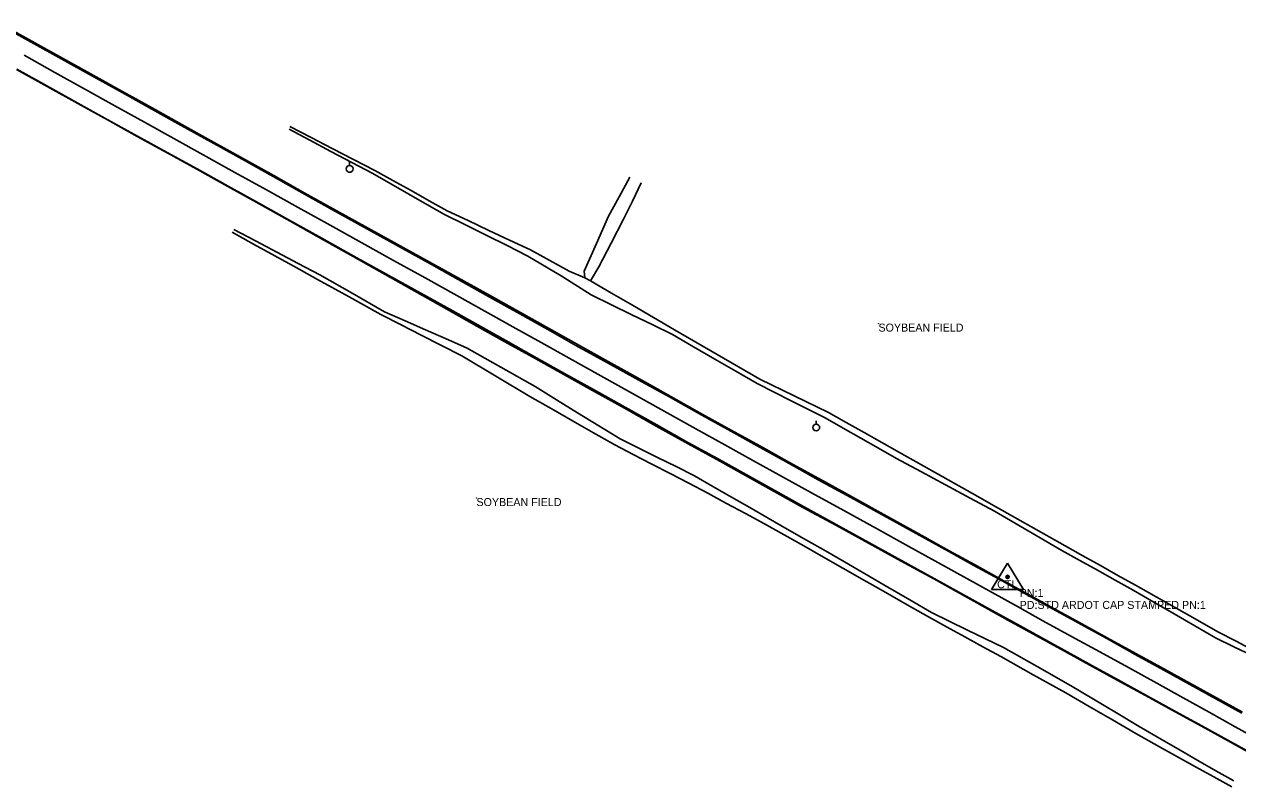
# Model space of a CAD drawing. Extents: x 1411444 to 1458157, y 300965 to 327300.
# Drawn here: x 1452975 to 1453733, y 303315 to 303791 of the extents above; entities that cross this region are included whole.
import ezdxf

# ---------------------------------------------------------------- set-up
doc = ezdxf.new("R2010")
doc.units = 0
for name, color, linetype in [('S_DITCHLINE', 7, 'Continuous'), ('S_EDGE_PAVEMENT', 7, 'Continuous'), ('S_MSC_PT_SYM', 7, 'Continuous'), ('S_PAVEMENT_CROWN', 7, 'Continuous'), ('S_PRIMARY_CTL', 7, 'Continuous'), ('S_PRIMARY_CTL_ANNOT', 7, 'Continuous'), ('S_SHOULDER', 7, 'Continuous'), ('S_SURVEY_TEXT_ANNOT', 7, 'Continuous'), ('S_UTILITY_POLE', 7, 'Continuous')]:
    doc.layers.add(name, color=color, linetype=linetype)

msp = doc.modelspace()

# ---------------------------------------------------------------- linework, layer by layer
at = {"layer": 'S_DITCHLINE'}
for points in [[(1453141.09, 303727.61), (1453154.33, 303720.74), (1453167.58, 303713.87), (1453180.83, 303706.99), (1453194.08, 303700.12), (1453205.42, 303693.81), (1453216.76, 303687.5), (1453228.1, 303681.19), (1453239.44, 303674.88), (1453252.42, 303668.76), (1453265.39, 303662.64), (1453278.37, 303656.53), (1453291.35, 303650.41), (1453303.47, 303643.81), (1453315.6, 303637.22), (1453325.3, 303633.05), (1453328.86, 303631.15), (1453341.98, 303623.5), (1453355.1, 303615.86), (1453368.22, 303608.22), (1453381.34, 303600.57), (1453394.67, 303592.82), (1453408, 303585.06), (1453421.33, 303577.31), (1453434.66, 303569.56), (1453456.1, 303559.14), (1453477.55, 303548.72), (1453488.67, 303542.47), (1453499.8, 303536.22), (1453510.93, 303529.97), (1453522.05, 303523.72), (1453537.19, 303515.2), (1453552.33, 303506.68), (1453567.47, 303498.16), (1453582.61, 303489.64), (1453604.08, 303477.53), (1453625.55, 303465.42), (1453636.5, 303459.26), (1453647.46, 303453.11), (1453658.41, 303446.95), (1453669.37, 303440.8), (1453682.26, 303433.51), (1453695.15, 303426.22), (1453708.04, 303418.94), (1453720.93, 303411.65), (1453732.25, 303405.79), (1453743.57, 303399.94)], [(1453140.54, 303725.91), (1453153.65, 303718.98), (1453166.77, 303712.05), (1453179.88, 303705.12), (1453193, 303698.19), (1453204.2, 303691.77), (1453215.39, 303685.35), (1453226.59, 303678.93), (1453237.78, 303672.51), (1453250.8, 303666.04), (1453263.81, 303659.57), (1453276.83, 303653.1), (1453289.84, 303646.63), (1453310.56, 303634.31), (1453329.37, 303622.31), (1453342.06, 303616.11), (1453354.76, 303609.92), (1453367.45, 303603.73), (1453380.14, 303597.53), (1453393.34, 303589.87), (1453406.54, 303582.22), (1453419.74, 303574.56), (1453432.94, 303566.9), (1453454.25, 303556.17), (1453475.55, 303545.43), (1453486.67, 303539.11), (1453497.79, 303532.8), (1453508.91, 303526.48), (1453520.03, 303520.16), (1453535.37, 303511.9), (1453550.7, 303503.63), (1453566.03, 303495.37), (1453581.36, 303487.1), (1453602.42, 303474.84), (1453623.48, 303462.59), (1453634.59, 303456.39), (1453645.69, 303450.19), (1453656.8, 303443.99), (1453667.91, 303437.8), (1453680.76, 303430.34), (1453693.61, 303422.89), (1453706.45, 303415.44), (1453719.3, 303407.99), (1453730.77, 303402.44), (1453742.23, 303396.89)], [(1453353.38, 303695.85), (1453346.77, 303683.72), (1453340.16, 303671.59), (1453332.56, 303654.35), (1453324.96, 303637.11), (1453325.28, 303633.06)], [(1453360.63, 303692.29), (1453355.04, 303680.94), (1453349.45, 303669.6), (1453341.81, 303654.71), (1453334.17, 303639.82), (1453328.89, 303631.12)], [(1453104.96, 303661.46), (1453118.32, 303654.1), (1453131.69, 303646.75), (1453145.06, 303639.4), (1453158.42, 303632.05), (1453178.13, 303621.06), (1453197.84, 303610.07), (1453210.52, 303603.6), (1453223.19, 303597.13), (1453235.87, 303590.66), (1453248.54, 303584.19), (1453269.79, 303571.49), (1453291.03, 303558.79), (1453304.29, 303551.23), (1453317.56, 303543.67), (1453330.82, 303536.11), (1453344.08, 303528.56), (1453355.64, 303522.58), (1453367.19, 303516.6), (1453378.74, 303510.62), (1453390.3, 303504.65), (1453402.13, 303498.31), (1453413.97, 303491.98), (1453425.81, 303485.64), (1453437.65, 303479.31), (1453449.89, 303472.35), (1453462.14, 303465.39), (1453474.38, 303458.43), (1453486.63, 303451.47), (1453499.99, 303443.88), (1453513.36, 303436.29), (1453526.73, 303428.7), (1453540.09, 303421.11), (1453551.39, 303414.89), (1453562.68, 303408.66), (1453573.98, 303402.44), (1453585.27, 303396.21), (1453605.56, 303384.9), (1453625.85, 303373.58), (1453640.46, 303365.14), (1453655.08, 303356.69), (1453669.7, 303348.24), (1453684.32, 303339.8), (1453695.65, 303333.57), (1453706.97, 303327.35), (1453718.3, 303321.12), (1453729.63, 303314.9)], [(1453106.11, 303663.12), (1453119.5, 303656.05), (1453132.9, 303648.99), (1453146.3, 303641.92), (1453159.7, 303634.85), (1453179.95, 303623.34), (1453200.19, 303611.82), (1453213.01, 303606.18), (1453225.82, 303600.54), (1453238.63, 303594.89), (1453251.44, 303589.25), (1453272.84, 303577.12), (1453294.23, 303564.99), (1453307.56, 303556.81), (1453320.88, 303548.63), (1453334.2, 303540.46), (1453347.52, 303532.28), (1453359.12, 303526.51), (1453370.72, 303520.75), (1453382.32, 303514.99), (1453393.93, 303509.23), (1453405.43, 303502.61), (1453416.94, 303495.98), (1453428.45, 303489.36), (1453439.95, 303482.74), (1453451.87, 303475.93), (1453463.78, 303469.12), (1453475.69, 303462.32), (1453487.6, 303455.51), (1453501.18, 303447.57), (1453514.76, 303439.64), (1453528.34, 303431.7), (1453541.92, 303423.76), (1453564.4, 303412.84), (1453586.87, 303401.92), (1453607.87, 303390.02), (1453628.88, 303378.11), (1453643.17, 303369.62), (1453657.45, 303361.13), (1453671.74, 303352.64), (1453686.03, 303344.14), (1453697.24, 303337.74), (1453708.44, 303331.33), (1453719.64, 303324.93), (1453730.84, 303318.52)]]:
    msp.add_lwpolyline(points, dxfattribs=at)
at = {"layer": 'S_EDGE_PAVEMENT'}
for points in [[(1452960.28, 303790.99), (1452979.46, 303780.33), (1452998.65, 303769.67), (1453017.83, 303759.01), (1453036.3, 303748.76), (1453054.78, 303738.51), (1453073.26, 303728.26), (1453091.73, 303718.01), (1453111.21, 303707.14), (1453130.68, 303696.26), (1453150.15, 303685.39), (1453169.63, 303674.51), (1453189.61, 303663.42), (1453209.59, 303652.34), (1453229.57, 303641.25), (1453249.55, 303630.16), (1453267.12, 303620.32), (1453284.69, 303610.47), (1453302.27, 303600.63), (1453319.84, 303590.78), (1453339.5, 303579.89), (1453359.15, 303569), (1453378.81, 303558.1), (1453398.47, 303547.21), (1453416.65, 303537.11), (1453434.82, 303527.01), (1453453, 303516.92), (1453471.18, 303506.82), (1453491.57, 303495.6), (1453511.96, 303484.38), (1453532.35, 303473.17), (1453552.75, 303461.95), (1453568.46, 303453.26), (1453584.17, 303444.57), (1453599.88, 303435.88), (1453615.59, 303427.19), (1453633.49, 303417.33), (1453651.39, 303407.46), (1453669.28, 303397.6), (1453687.18, 303387.73), (1453703.41, 303378.78), (1453719.65, 303369.82), (1453735.88, 303360.87)], [(1452970.4, 303763.42), (1452989.55, 303752.77), (1453008.69, 303742.11), (1453027.28, 303731.84), (1453045.88, 303721.57), (1453064.47, 303711.3), (1453083.06, 303701.03), (1453102.54, 303690.2), (1453122.03, 303679.38), (1453141.51, 303668.55), (1453160.99, 303657.73), (1453180.99, 303646.63), (1453200.99, 303635.54), (1453220.99, 303624.45), (1453240.99, 303613.35), (1453258.45, 303603.6), (1453275.91, 303593.84), (1453293.37, 303584.08), (1453310.83, 303574.33), (1453330.68, 303563.23), (1453350.53, 303552.13), (1453370.38, 303541.04), (1453390.23, 303529.94), (1453408.19, 303519.98), (1453426.15, 303510.02), (1453444.11, 303500.06), (1453462.06, 303490.1), (1453482.47, 303478.86), (1453502.88, 303467.63), (1453523.28, 303456.39), (1453543.69, 303445.15), (1453559.53, 303436.37), (1453575.37, 303427.58), (1453591.21, 303418.79), (1453607.05, 303410), (1453624.83, 303400.24), (1453642.6, 303390.48), (1453660.37, 303380.72), (1453678.15, 303370.96), (1453694.47, 303361.98), (1453710.79, 303352.99), (1453727.11, 303344), (1453743.43, 303335.02)]]:
    msp.add_lwpolyline(points, dxfattribs=at)
at = {"layer": 'S_MSC_PT_SYM'}
for points in [[(1453508.8, 303604.38), (1453508.8, 303604.43), (1453508.8, 303604.38), (1453508.75, 303604.38), (1453508.8, 303604.38), (1453508.8, 303604.33), (1453508.8, 303604.38), (1453508.85, 303604.38)], [(1453257.66, 303495.34), (1453257.66, 303495.39), (1453257.66, 303495.34), (1453257.61, 303495.34), (1453257.66, 303495.34), (1453257.66, 303495.29), (1453257.66, 303495.34), (1453257.71, 303495.34)]]:
    msp.add_lwpolyline(points, dxfattribs=at)
at = {"layer": 'S_PAVEMENT_CROWN'}
msp.add_lwpolyline([(1452975.1, 303772.08), (1452994.25, 303761.41), (1453013.41, 303750.75), (1453031.78, 303740.54), (1453050.15, 303730.34), (1453068.52, 303720.14), (1453086.89, 303709.93), (1453106.7, 303698.93), (1453126.52, 303687.92), (1453146.34, 303676.92), (1453166.16, 303665.92), (1453185.97, 303654.91), (1453205.79, 303643.91), (1453225.61, 303632.9), (1453245.43, 303621.9), (1453262.95, 303612.11), (1453280.47, 303602.31), (1453298, 303592.52), (1453315.52, 303582.73), (1453335.34, 303571.72), (1453355.16, 303560.71), (1453374.98, 303549.7), (1453394.8, 303538.7), (1453412.82, 303528.69), (1453430.84, 303518.67), (1453448.86, 303508.66), (1453466.88, 303498.65), (1453487.22, 303487.46), (1453507.55, 303476.27), (1453527.88, 303465.08), (1453548.22, 303453.89), (1453564.04, 303445.09), (1453579.86, 303436.29), (1453595.68, 303427.49), (1453611.5, 303418.69), (1453629.33, 303408.91), (1453647.17, 303399.12), (1453665, 303389.33), (1453682.83, 303379.55), (1453699.11, 303370.5), (1453715.38, 303361.46), (1453731.65, 303352.42), (1453747.93, 303343.37)], dxfattribs=at)
at = {"layer": 'S_PRIMARY_CTL'}
for p, q in [((1453589.52, 303454.74), (1453579.49, 303438.22)), ((1453589.52, 303454.74), (1453599.35, 303438.22)), ((1453579.49, 303438.22), (1453599.35, 303438.22))]:
    msp.add_line(p, q, dxfattribs=at)
for radius in [1.04, 0.609, 0.344]:
    msp.add_circle((1453589.52, 303446.04), radius, dxfattribs=at)
at = {"layer": 'S_SHOULDER'}
for points in [[(1452960.63, 303791.49), (1452979.79, 303780.87), (1452998.95, 303770.25), (1453018.12, 303759.63), (1453036.59, 303749.39), (1453055.06, 303739.15), (1453073.53, 303728.9), (1453092, 303718.66), (1453111.49, 303707.77), (1453130.98, 303696.88), (1453150.47, 303685.99), (1453169.96, 303675.11), (1453189.98, 303664.05), (1453209.99, 303652.99), (1453230.01, 303641.93), (1453250.03, 303630.87), (1453267.58, 303621.09), (1453285.14, 303611.3), (1453302.69, 303601.52), (1453320.24, 303591.73), (1453339.85, 303580.75), (1453359.45, 303569.76), (1453379.05, 303558.77), (1453398.66, 303547.79), (1453416.87, 303537.74), (1453435.09, 303527.69), (1453453.3, 303517.64), (1453471.52, 303507.6), (1453491.88, 303496.3), (1453512.24, 303485.01), (1453532.6, 303473.71), (1453552.96, 303462.42), (1453568.72, 303453.73), (1453584.49, 303445.04), (1453600.25, 303436.35), (1453616.02, 303427.66), (1453633.9, 303417.83), (1453651.78, 303407.99), (1453669.67, 303398.15), (1453687.55, 303388.32), (1453703.75, 303379.35), (1453719.96, 303370.38), (1453736.16, 303361.41)], [(1452970.34, 303763.28), (1452989.49, 303752.62), (1453008.64, 303741.97), (1453027.2, 303731.68), (1453045.77, 303721.39), (1453064.33, 303711.11), (1453082.9, 303700.82), (1453102.37, 303689.98), (1453121.84, 303679.14), (1453141.32, 303668.31), (1453160.79, 303657.47), (1453180.72, 303646.23), (1453200.64, 303634.99), (1453220.57, 303623.75), (1453240.5, 303612.51), (1453257.96, 303602.79), (1453275.42, 303593.07), (1453292.88, 303583.34), (1453310.34, 303573.62), (1453330.24, 303562.54), (1453350.13, 303551.46), (1453370.03, 303540.37), (1453389.93, 303529.29), (1453407.86, 303519.34), (1453425.78, 303509.39), (1453443.71, 303499.44), (1453461.64, 303489.5), (1453482.1, 303478.31), (1453502.55, 303467.13), (1453523.01, 303455.95), (1453543.46, 303444.77), (1453559.46, 303435.87), (1453575.46, 303426.97), (1453591.46, 303418.07), (1453607.46, 303409.17), (1453625.07, 303399.54), (1453642.67, 303389.9), (1453660.28, 303380.27), (1453677.88, 303370.63), (1453694.24, 303361.65), (1453710.6, 303352.67), (1453726.96, 303343.7), (1453743.32, 303334.72)]]:
    msp.add_lwpolyline(points, dxfattribs=at)
at = {"layer": 'S_UTILITY_POLE'}
for p, q in [((1453178.3, 303703.23), (1453178.3, 303705.34)), ((1453469.79, 303541.58), (1453469.79, 303543.69))]:
    msp.add_line(p, q, dxfattribs=at)
for centre in [(1453178.42, 303701.09), (1453469.92, 303539.44)]:
    msp.add_circle(centre, 2.13, dxfattribs=at)

# ---------------------------------------------------------------- texts
at = {"layer": 'S_PRIMARY_CTL'}
msp.add_text('CTL', height=5, rotation=360, dxfattribs=at).set_placement((1453582.94, 303438.96))
at = {"layer": 'S_PRIMARY_CTL_ANNOT'}
for s, p in [('PN:1', (1453597.02, 303433.54)), ('PD:STD ARDOT CAP STAMPED PN:1', (1453597.02, 303426.04))]:
    msp.add_text(s, height=5, dxfattribs=at).set_placement(p)
at = {"layer": 'S_SURVEY_TEXT_ANNOT'}
for p in [(1453508.8, 303599.38), (1453257.66, 303490.34)]:
    msp.add_text('SOYBEAN FIELD', height=5, dxfattribs=at).set_placement(p)

doc.saveas('drawing.dxf')
